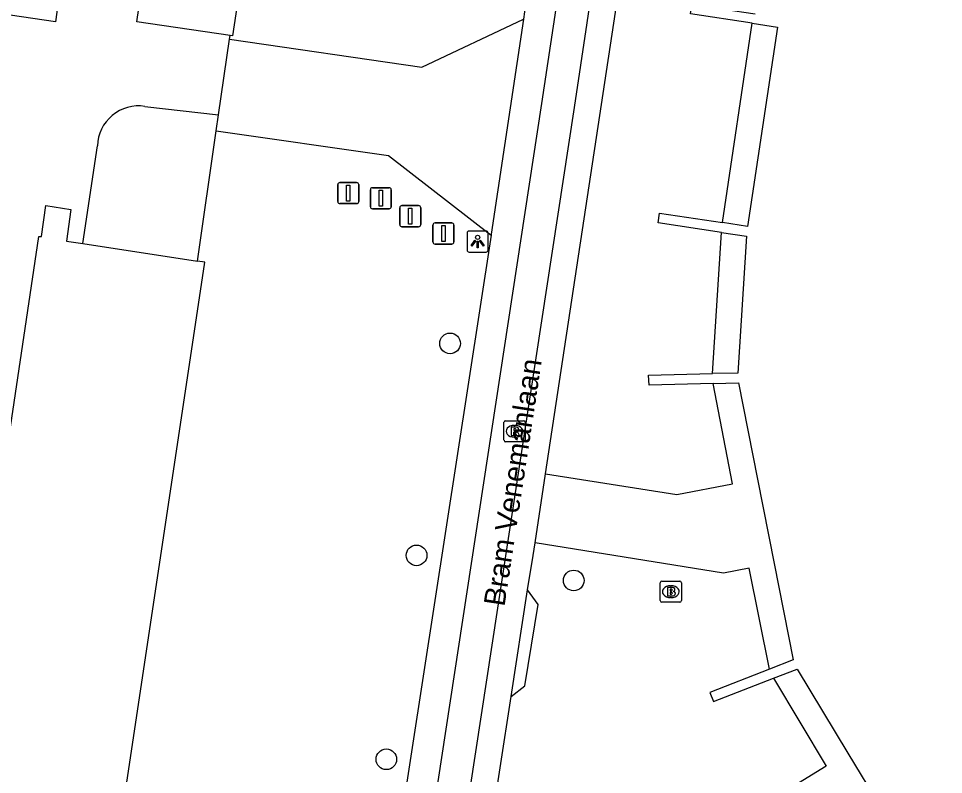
# Model space of a CAD drawing. Extents: x 161094 to 161705, y 379509 to 380907.
# Drawn here: x 161459.2 to 161503, y 380315.44 to 380351.25 of the extents above; entities that cross this region are included whole.
import ezdxf

# ---------------------------------------------------------------- set-up
doc = ezdxf.new("R2010")
doc.units = 0
for name, color, linetype in [('IMGEO_Afsluitpaal', 7, 'Continuous'), ('IMGEO_Boom', 7, 'Continuous'), ('IMGEO_Brandkraan', 7, 'Continuous'), ('IMGEO_Hek', 7, 'Continuous'), ('IMGEO_Lichtpunt', 7, 'Continuous'), ('IMGEO_Openbare_ruimte_label', 7, 'Continuous'), ('IMGEO_Pand', 7, 'Continuous'), ('IMGEO_Rijbaan_lokaal_gesloten', 7, 'Continuous'), ('IMGEO_Rijbaan_lokaal_open', 7, 'Continuous'), ('IMGEO_Rioolput', 7, 'Continuous'), ('IMGEO_Voetpad_gesloten', 7, 'Continuous'), ('IMGEO_Voetpad_open', 7, 'Continuous')]:
    doc.layers.add(name, color=color, linetype=linetype)

msp = doc.modelspace()

# ---------------------------------------------------------------- linework, layer by layer
at = {"layer": 'IMGEO_Afsluitpaal'}
for p, q in [((161474.317, 380342.579), (161474.317, 380343.379)), ((161474.317, 380343.379), (161474.317, 380342.579)), ((161474.417, 380343.479), (161475.207, 380343.479)), ((161475.207, 380343.479), (161474.417, 380343.479)), ((161475.307, 380343.379), (161475.307, 380342.579)), ((161475.307, 380342.579), (161475.307, 380343.379)), ((161475.86, 380342.336), (161475.86, 380343.136)), ((161475.86, 380343.136), (161475.86, 380342.336)), ((161475.96, 380343.236), (161476.75, 380343.236)), ((161476.75, 380343.236), (161475.96, 380343.236)), ((161476.85, 380343.136), (161476.85, 380342.336)), ((161476.85, 380342.336), (161476.85, 380343.136)), ((161475.207, 380342.479), (161474.417, 380342.479)), ((161474.417, 380342.479), (161475.207, 380342.479)), ((161476.75, 380342.236), (161475.96, 380342.236)), ((161475.96, 380342.236), (161476.75, 380342.236)), ((161477.253, 380341.489), (161477.253, 380342.289)), ((161477.253, 380342.289), (161477.253, 380341.489)), ((161477.353, 380342.389), (161478.143, 380342.389)), ((161478.143, 380342.389), (161477.353, 380342.389)), ((161478.243, 380342.289), (161478.243, 380341.489)), ((161478.243, 380341.489), (161478.243, 380342.289)), ((161478.143, 380341.389), (161477.353, 380341.389)), ((161477.353, 380341.389), (161478.143, 380341.389)), ((161478.824, 380340.663), (161478.824, 380341.463)), ((161478.824, 380341.463), (161478.824, 380340.663)), ((161478.924, 380341.563), (161479.714, 380341.563)), ((161479.714, 380341.563), (161478.924, 380341.563)), ((161479.814, 380341.463), (161479.814, 380340.663)), ((161479.814, 380340.663), (161479.814, 380341.463)), ((161479.714, 380340.563), (161478.924, 380340.563)), ((161478.924, 380340.563), (161479.714, 380340.563))]:
    msp.add_line(p, q, dxfattribs=at)
for points in [[(161474.737, 380343.354), (161474.887, 380343.354), (161474.887, 380342.604), (161474.737, 380342.604), (161474.737, 380343.354)], [(161476.28, 380343.111), (161476.43, 380343.111), (161476.43, 380342.361), (161476.28, 380342.361), (161476.28, 380343.111)], [(161477.673, 380342.264), (161477.823, 380342.264), (161477.823, 380341.514), (161477.673, 380341.514), (161477.673, 380342.264)], [(161479.244, 380341.438), (161479.394, 380341.438), (161479.394, 380340.688), (161479.244, 380340.688), (161479.244, 380341.438)]]:
    msp.add_lwpolyline(points, dxfattribs=at)
for centre, start, end in [((161474.417, 380343.379), 90, 180), ((161474.417, 380343.379), 90, 180), ((161475.207, 380343.379), 0, 90), ((161475.207, 380343.379), 360, 90), ((161475.96, 380343.136), 90, 180), ((161475.96, 380343.136), 90, 180), ((161476.75, 380343.136), 0, 90), ((161476.75, 380343.136), 360, 90), ((161474.417, 380342.579), 180, 270), ((161474.417, 380342.579), 180, 270), ((161475.207, 380342.579), 270, 0), ((161475.207, 380342.579), 270, 0), ((161475.96, 380342.336), 180, 270), ((161475.96, 380342.336), 180, 270), ((161476.75, 380342.336), 270, 0), ((161476.75, 380342.336), 270, 0), ((161477.353, 380342.289), 90, 180), ((161477.353, 380342.289), 90, 180), ((161478.143, 380342.289), 0, 90), ((161478.143, 380342.289), 360, 90), ((161477.353, 380341.489), 180, 270), ((161477.353, 380341.489), 180, 270), ((161478.143, 380341.489), 270, 0), ((161478.143, 380341.489), 270, 0), ((161478.924, 380341.463), 90, 180), ((161478.924, 380341.463), 90, 180), ((161479.714, 380341.463), 0, 90), ((161479.714, 380341.463), 360, 90), ((161478.924, 380340.663), 180, 270), ((161478.924, 380340.663), 180, 270), ((161479.714, 380340.663), 270, 0), ((161479.714, 380340.663), 270, 0)]:
    msp.add_arc(centre, 0.1, start, end, dxfattribs=at)
at = {"layer": 'IMGEO_Boom'}
for centre in [(161479.634, 380335.858), (161478.047, 380325.817), (161485.488, 380324.628), (161476.616, 380316.155)]:
    msp.add_circle(centre, 0.489, dxfattribs=at)
at = {"layer": 'IMGEO_Brandkraan'}
for p, q in [((161489.584, 380323.671), (161489.584, 380324.523)), ((161489.659, 380324.597), (161490.511, 380324.597)), ((161490.072, 380324.377), (161490.097, 380324.377)), ((161490.585, 380324.523), (161490.585, 380323.671)), ((161490.095, 380323.817), (161490.07, 380323.817)), ((161490.511, 380323.597), (161489.659, 380323.597))]:
    msp.add_line(p, q, dxfattribs=at)
for points in [[(161489.584, 380323.671), (161489.584, 380324.523)], [(161489.659, 380324.597), (161490.511, 380324.597)], [(161489.932, 380324.297), (161489.932, 380323.897), (161490.145, 380323.897)], [(161490.163, 380324.297), (161489.932, 380324.297)], [(161490.585, 380324.523), (161490.585, 380323.671)], [(161490.111, 380324.216), (161490.057, 380324.216), (161490.057, 380324.14)], [(161490.057, 380324.14), (161490.11, 380324.14)], [(161490.119, 380324.064), (161490.057, 380324.064), (161490.057, 380323.983)], [(161490.057, 380323.983), (161490.119, 380323.983)], [(161490.511, 380323.597), (161489.659, 380323.597)]]:
    msp.add_lwpolyline(points, dxfattribs=at)
for centre, radius, start, end in [((161489.661, 380324.521), 0.0765, 91.552, 178.448), ((161489.661, 380324.521), 0.0765, 91.552, 178.448), ((161490.167, 380324.152), 0.145, 59.4692, 91.5367), ((161490.192, 380324.199), 0.0922, 285.5137, 58.1501), ((161490.509, 380324.521), 0.0765, 1.552, 88.448), ((161490.509, 380324.521), 0.0765, 1.552, 88.448), ((161490.112, 380324.178), 0.0379, 267.8285, 90.9355), ((161490.12, 380324.023), 0.0404, 269.8759, 90.5077), ((161490.151, 380324.148), 0.251, 268.6676, 293.5347), ((161490.197, 380324.007), 0.105, 301.3115, 78.989), ((161489.661, 380323.673), 0.0765, 181.552, 268.448), ((161489.661, 380323.673), 0.0765, 181.552, 268.448), ((161490.509, 380323.673), 0.0765, 271.552, 358.448), ((161490.509, 380323.673), 0.0765, 271.552, 358.448)]:
    msp.add_arc(centre, radius, start, end, dxfattribs=at)
for centre, major_axis, ratio, start_param, end_param in [((161490.071, 380324.097), (-0.387, 0.002), 0.722429, 4.712389, 7.853982), ((161490.096, 380324.097), (-0.39, 0.002), 0.717154, 1.570796, 4.712389)]:
    msp.add_ellipse(centre, major_axis=major_axis, ratio=ratio, start_param=start_param, end_param=end_param, dxfattribs=at)
at = {"layer": 'IMGEO_Hek'}
for points in [[(161468.673, 380346.684), (161469.191, 380350.273)], [(161469.191, 380350.273), (161469.216, 380350.446)], [(161468.564, 380345.931), (161468.673, 380346.684)], [(161467.674, 380339.759), (161468.564, 380345.931)]]:
    msp.add_lwpolyline(points, dxfattribs=at)
at = {"layer": 'IMGEO_Lichtpunt'}
for p, q in [((161480.44, 380341.088), (161480.44, 380340.281)), ((161480.44, 380341.088), (161480.44, 380340.281)), ((161481.342, 380341.183), (161480.534, 380341.183)), ((161481.342, 380341.183), (161480.534, 380341.183)), ((161481.436, 380340.281), (161481.436, 380341.088)), ((161481.436, 380340.281), (161481.436, 380341.088)), ((161480.534, 380340.187), (161481.342, 380340.187)), ((161480.534, 380340.187), (161481.342, 380340.187))]:
    msp.add_line(p, q, dxfattribs=at)
for points in [[(161480.814, 380340.752), (161480.853, 380340.724), (161480.665, 380340.462), (161480.627, 380340.489), (161480.814, 380340.752)], [(161480.916, 380340.704), (161480.963, 380340.704), (161480.963, 380340.382), (161480.916, 380340.382), (161480.916, 380340.704)], [(161481.026, 380340.724), (161481.064, 380340.751), (161481.251, 380340.489), (161481.212, 380340.461), (161481.026, 380340.724)]]:
    msp.add_lwpolyline(points, dxfattribs=at)
msp.add_circle((161480.939, 380340.886), 0.0994, dxfattribs=at)
for centre, start, end in [((161480.534, 380341.088), 90, 180), ((161480.534, 380341.088), 90, 180), ((161481.342, 380341.088), 0, 90), ((161481.342, 380341.088), 0, 90), ((161480.534, 380340.281), 180, 270), ((161480.534, 380340.281), 180, 270), ((161481.342, 380340.281), 270, 0), ((161481.342, 380340.281), 270, 360)]:
    msp.add_arc(centre, 0.0946, start, end, dxfattribs=at)
at = {"layer": 'IMGEO_Pand'}
for points in [[(161469.216, 380350.446), (161464.796, 380351.094), (161466.132, 380360.169)], [(161470.678, 380359.631), (161470.715, 380359.626), (161469.332, 380350.429), (161469.216, 380350.446)], [(161493.943, 380351.023), (161491.02, 380351.468), (161491.087, 380351.92), (161494.074, 380351.47)], [(161493.943, 380351.023), (161495.129, 380350.843), (161493.724, 380341.399), (161492.538, 380341.579)], [(161458.225, 380327.954), (161460.165, 380340.92), (161460.282, 380340.917), (161460.497, 380342.387), (161461.676, 380342.209), (161461.477, 380340.701), (161462.242, 380340.585)], [(161492.487, 380341.117), (161489.494, 380341.575), (161489.557, 380342.03), (161492.538, 380341.579)], [(161492.487, 380341.117), (161493.673, 380340.935), (161493.254, 380334.455), (161492.054, 380334.428)], [(161462.242, 380340.585), (161467.674, 380339.759)], [(161445.404, 380233.707), (161445.627, 380235.147), (161446.05, 380235.084), (161452.191, 380234.169), (161452.226, 380234.4), (161454.566, 380250), (161468.027, 380339.705), (161467.674, 380339.759)], [(161492.093, 380333.96), (161489.054, 380333.883), (161489.035, 380334.359), (161492.054, 380334.428)], [(161492.093, 380333.96), (161493.293, 380333.99), (161494.191, 380329.43), (161494.977, 380325.436), (161495.877, 380320.867), (161494.759, 380320.431)], [(161494.759, 380320.431), (161491.927, 380319.326), (161492.102, 380318.889), (161494.951, 380319.996)], [(161494.951, 380319.996), (161496.069, 380320.431), (161498.471, 380316.454), (161500, 380313.923), (161502.996, 380308.963), (161502.074, 380308.157)]]:
    msp.add_lwpolyline(points, dxfattribs=at)
at = {"layer": 'IMGEO_Rijbaan_lokaal_gesloten'}
for points in [[(161500.797, 380441.248), (161498.535, 380426.719), (161497.303, 380424.898), (161496.967, 380422.687), (161487.325, 380359.344), (161487.307, 380359.083), (161485.505, 380347.041), (161467.599, 380229.99), (161457.567, 380164.364), (161456.074, 380164.596), (161466.094, 380230.202), (161483.979, 380347.225), (161485.809, 380359.378), (161485.861, 380359.57), (161495.524, 380423.042), (161498.373, 380441.757)], [(161484.786, 380360.785), (161484.635, 380359.832), (161484.508, 380359.848), (161483.159, 380351.566), (161483.106, 380351.212)], [(161484.156, 380329.687), (161488.137, 380355.942)], [(161483.106, 380351.212), (161481.581, 380341.038), (161481.572, 380340.98)], [(161481.572, 380340.98), (161477.293, 380313.127), (161475.319, 380300.52), (161473.666, 380289.12)], [(161483.658, 380326.406), (161484.156, 380329.687)], [(161483.303, 380324.182), (161483.568, 380325.811), (161483.658, 380326.406)], [(161482.528, 380319.134), (161483.303, 380324.182)], [(161481.485, 380312.377), (161482.528, 380319.134)]]:
    msp.add_lwpolyline(points, dxfattribs=at)
at = {"layer": 'IMGEO_Rijbaan_lokaal_open'}
for points in [[(161469.191, 380350.273), (161478.299, 380348.952), (161483.106, 380351.212)], [(161468.673, 380346.684), (161469.191, 380350.273)], [(161468.564, 380345.931), (161468.673, 380346.684)], [(161468.564, 380345.931), (161476.723, 380344.754), (161481.572, 380340.98)], [(161482.528, 380319.134), (161483.174, 380319.641), (161483.799, 380323.487), (161483.303, 380324.182)]]:
    msp.add_lwpolyline(points, dxfattribs=at)
at = {"layer": 'IMGEO_Rioolput'}
for p, q in [((161482.187, 380331.268), (161482.187, 380332.12)), ((161482.262, 380332.194), (161483.114, 380332.194)), ((161483.188, 380332.12), (161483.188, 380331.268)), ((161482.675, 380331.974), (161482.7, 380331.974)), ((161482.698, 380331.414), (161482.673, 380331.414)), ((161483.114, 380331.194), (161482.262, 380331.194))]:
    msp.add_line(p, q, dxfattribs=at)
for points in [[(161482.187, 380331.268), (161482.187, 380332.12)], [(161482.262, 380332.194), (161483.114, 380332.194)], [(161483.188, 380332.12), (161483.188, 380331.268)], [(161482.776, 380331.892), (161482.524, 380331.894), (161482.524, 380331.494)], [(161482.702, 380331.813), (161482.648, 380331.813), (161482.648, 380331.732)], [(161482.648, 380331.732), (161482.7, 380331.732)], [(161482.524, 380331.494), (161482.648, 380331.494), (161482.648, 380331.656), (161482.659, 380331.656)], [(161482.706, 380331.627), (161482.777, 380331.494), (161482.917, 380331.494), (161482.852, 380331.62)], [(161483.114, 380331.194), (161482.262, 380331.194)]]:
    msp.add_lwpolyline(points, dxfattribs=at)
for centre, radius, start, end in [((161482.264, 380332.118), 0.0765, 91.552, 178.448), ((161482.264, 380332.118), 0.0765, 91.552, 178.448), ((161483.112, 380332.118), 0.0765, 1.552, 88.448), ((161483.112, 380332.118), 0.0765, 1.552, 88.448), ((161482.684, 380331.921), 0.19, 274.7715, 282.9687), ((161482.708, 380331.717), 0.0964, 77.0061, 93.1865), ((161482.722, 380331.774), 0.0378, 276.6634, 79.6772), ((161482.775, 380331.782), 0.109, 350.3612, 89.416), ((161482.773, 380331.782), 0.112, 277.5842, 350.9817), ((161482.264, 380331.27), 0.0765, 181.552, 268.448), ((161482.264, 380331.27), 0.0765, 181.552, 268.448), ((161482.658, 380331.603), 0.0533, 26.0293, 88.6989), ((161482.757, 380331.567), 0.108, 29.5134, 73.7905), ((161483.112, 380331.27), 0.0765, 271.552, 358.448), ((161483.112, 380331.27), 0.0765, 271.552, 358.448)]:
    msp.add_arc(centre, radius, start, end, dxfattribs=at)
for centre, major_axis, ratio, start_param, end_param in [((161482.674, 380331.694), (-0.387, 0.002), 0.722429, 4.712389, 7.853982), ((161482.699, 380331.694), (-0.39, 0.002), 0.717154, 1.570796, 4.712389)]:
    msp.add_ellipse(centre, major_axis=major_axis, ratio=ratio, start_param=start_param, end_param=end_param, dxfattribs=at)
at = {"layer": 'IMGEO_Voetpad_gesloten'}
for points in [[(161461.102, 380352.136), (161460.946, 380351.094), (161448.797, 380352.894), (161449.083, 380354.725), (161436.203, 380356.676)], [(161469.191, 380350.273), (161469.216, 380350.446)], [(161465.187, 380347.087), (161468.673, 380346.684)], [(161462.242, 380340.585), (161462.936, 380345.213)]]:
    msp.add_lwpolyline(points, dxfattribs=at)
msp.add_arc((161464.889, 380345.157), 1.953, 81.2109, 178.3451, dxfattribs=at)
at = {"layer": 'IMGEO_Voetpad_open'}
for points in [[(161492.538, 380341.579), (161493.943, 380351.023)], [(161467.674, 380339.759), (161468.564, 380345.931)], [(161492.054, 380334.428), (161492.487, 380341.117)], [(161484.156, 380329.687), (161490.363, 380328.707), (161493.012, 380329.207), (161492.093, 380333.96)], [(161494.759, 380320.431), (161493.799, 380325.209), (161492.58, 380324.975), (161483.658, 380326.406)], [(161494.951, 380319.996), (161497.448, 380315.827), (161489.527, 380310.973), (161481.485, 380312.377)]]:
    msp.add_lwpolyline(points, dxfattribs=at)

# ---------------------------------------------------------------- texts
at = {"layer": 'IMGEO_Openbare_ruimte_label'}
msp.add_text('Bram Venemanlaan', height=1, rotation=81.3758, dxfattribs=at).set_placement((161482.208, 380323.364))

doc.saveas('drawing.dxf')
